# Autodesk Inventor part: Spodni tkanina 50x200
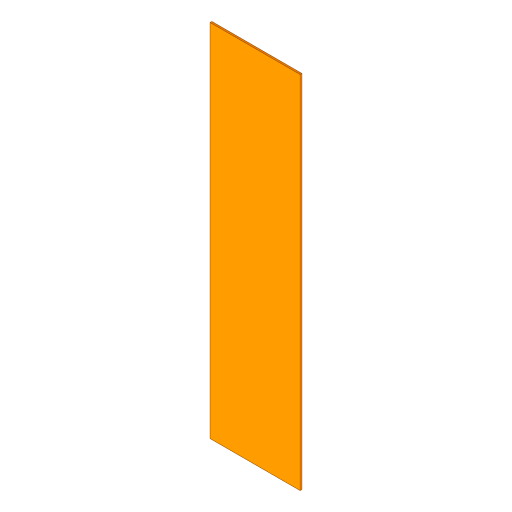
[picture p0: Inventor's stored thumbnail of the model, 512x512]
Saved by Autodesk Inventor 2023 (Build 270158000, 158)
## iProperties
Created: 2025-03
Part Number: Spodni tkanina 50x200
Material: Všeobecné
Document SubType Name: Modeling
Designer: tomik
Density: 1 g/cm^3
Appearance: Výchozí(1)
Author: tomik
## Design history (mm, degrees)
sketch "Náčrt1"
  geometry: L1 (25, -100)-(-25, -100); L2 (-25, -100)-(-25, 100); L3 (-25, 100)-(25, 100); L4 (25, 100)-(25, -100); L5 (25, -100)-(-25, 100); L6 (-25, -100)-(25, 100); 1 further point
  constraints: 12 end point, 2 midpoint, 2 parallel, 1 horizontal, 1 perpendicular
  dimensions: "d0" = 200 distance of L3.end L1.start; "d1" = 50 distance between parallel lines of L2 L4
extrude "Vysunutí1" new body sketch "Náčrt1" distance "d2" = 1; taper "d3" = 0 deg
node "Těleso1"
